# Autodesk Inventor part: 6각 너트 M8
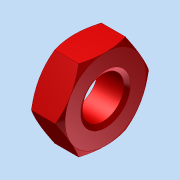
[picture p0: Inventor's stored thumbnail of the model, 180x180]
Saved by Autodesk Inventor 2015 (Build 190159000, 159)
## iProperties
Created: 2026-09
Part Number: 6각 너트 M8
Material: 일반
Document SubType Name: Modeling
Designer: SCD-A06
Density: 1 g/cm^3
Appearance: 기본값
Author: SCD-A06
Author: jhkim
Description: 6각 너트
Creation Date: 2026-08-27
Sending System: Autodesk Inventor 2027
Preprocessor: ST-DEVELOPER v20.1
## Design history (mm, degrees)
node "6각 너트 M81"
body "Solid1"
node "기준1"
